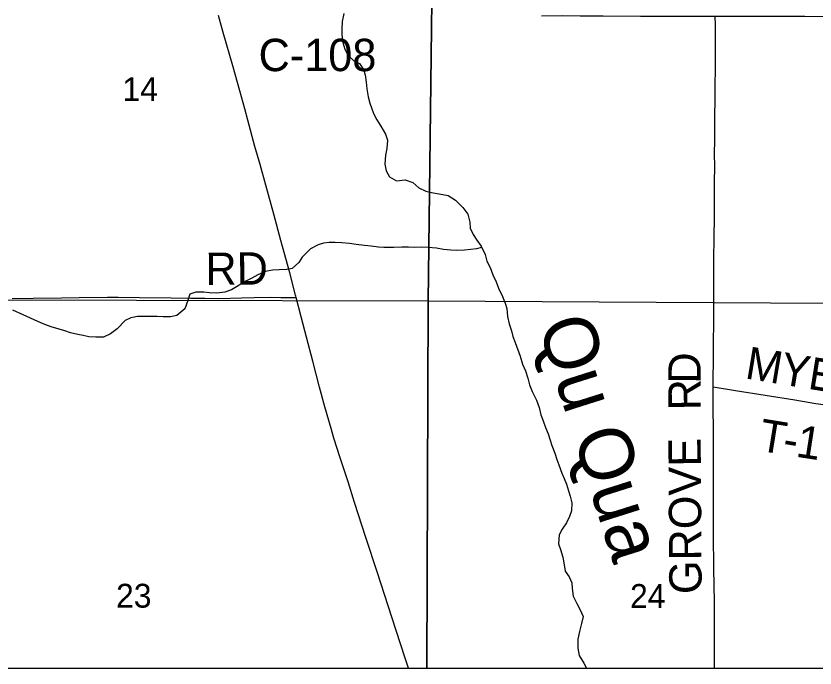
# Model space of a CAD drawing. Extents: x -9.1 to 34, y -3.1 to 22.
# Drawn here: x 6.461 to 7.865, y 14.1 to 15.245 of the extents above; entities that cross this region are included whole.
import ezdxf

# ---------------------------------------------------------------- set-up
doc = ezdxf.new("R2010")
doc.units = 0
for name, color, linetype in [('GM_X_County_Road', 7, 'Continuous'), ('GM_X_County_Road_Text', 7, 'Continuous'), ('GM_X_Minor_River', 7, 'Continuous'), ('GM_X_Minor_River_Text', 7, 'Continuous'), ('GM_X_Section', 7, 'Continuous'), ('GM_X_Section_Text', 7, 'Continuous'), ('GM_X_State_Route', 7, 'Continuous'), ('GM_X_Township', 7, 'Continuous'), ('GM_X_Township_Road', 7, 'Continuous'), ('GM_X_Township_Road_Text', 7, 'Continuous'), ('SH_Data', 7, 'Continuous')]:
    doc.layers.add(name, color=color, linetype=linetype)

msp = doc.modelspace()

# ---------------------------------------------------------------- linework, layer by layer
at = {"layer": 'GM_X_County_Road'}
for points in [[(7.3847, 15.2454), (7.4215, 15.2455), (7.4526, 15.2453), (7.4929, 15.2451), (7.5582, 15.2447), (7.6203, 15.2445), (7.6576, 15.2445), (7.6897, 15.2447)], [(7.6897, 15.2447), (7.6948, 15.2447), (7.757, 15.2443), (7.8098, 15.2443), (7.847, 15.2444), (7.8905, 15.244), (7.9185, 15.244), (7.9624, 15.2443)]]:
    msp.add_lwpolyline(points, dxfattribs=at)
at = {"layer": 'GM_X_Minor_River'}
for points in [[(7.0374, 15.2492), (7.0346, 15.2352), (7.0336, 15.2219), (7.0335, 15.2117), (7.0352, 15.1984), (7.0388, 15.1866), (7.0447, 15.1756), (7.0544, 15.1667), (7.065, 15.1616), (7.072, 15.1509), (7.0749, 15.1414), (7.0766, 15.1289), (7.0776, 15.1167), (7.0801, 15.1027), (7.0829, 15.092), (7.0862, 15.0821), (7.0902, 15.0722), (7.095, 15.0627), (7.1021, 15.0516), (7.1102, 15.0371), (7.1139, 15.0268), (7.1125, 15.012), (7.1105, 15.0003), (7.1091, 14.9848), (7.1116, 14.973), (7.1175, 14.9627), (7.1299, 14.9553), (7.1447, 14.957), (7.1586, 14.9527), (7.1691, 14.9434), (7.1812, 14.9372), (7.1914, 14.9348), (7.2046, 14.9327), (7.2205, 14.9298), (7.2336, 14.9217), (7.2463, 14.9083), (7.2548, 14.8968), (7.2584, 14.8827), (7.2594, 14.8721), (7.2646, 14.861), (7.2709, 14.8515), (7.2783, 14.8407), (7.2853, 14.8262), (7.2885, 14.8141), (7.2944, 14.803), (7.2992, 14.7901), (7.3051, 14.7782), (7.3087, 14.7672), (7.3157, 14.7523), (7.3205, 14.7409), (7.3234, 14.7314), (7.3247, 14.7173), (7.3279, 14.7044), (7.3319, 14.6918), (7.334, 14.6823), (7.338, 14.6717), (7.3468, 14.6473), (7.3512, 14.6336), (7.3563, 14.6218), (7.3607, 14.6088), (7.3635, 14.5974), (7.3683, 14.5856), (7.3756, 14.5703), (7.3804, 14.5574), (7.3836, 14.5448), (7.3876, 14.5338), (7.3916, 14.5224), (7.396, 14.5113), (7.4, 14.5003), (7.4029, 14.4908), (7.4077, 14.477), (7.4113, 14.4664)], [(7.2793, 14.8386), (7.2703, 14.8359), (7.2604, 14.8349), (7.249, 14.8339), (7.2358, 14.833), (7.2252, 14.8335), (7.2123, 14.8348), (7.1998, 14.8369), (7.1855, 14.8382), (7.1745, 14.8388), (7.1616, 14.8386), (7.151, 14.8387), (7.1393, 14.8392), (7.1248, 14.8383), (7.1078, 14.8382), (7.098, 14.8391), (7.0855, 14.8407), (7.0734, 14.842), (7.059, 14.8438), (7.0473, 14.8451), (7.0337, 14.8464), (7.0223, 14.8469), (7.0117, 14.8471), (7.0015, 14.8457), (6.992, 14.8432), (6.9786, 14.8358), (6.964, 14.8216), (6.9582, 14.8118), (6.9467, 14.8013), (6.9372, 14.8), (6.9239, 14.7994), (6.9122, 14.7988), (6.8996, 14.7963), (6.8863, 14.7904), (6.8756, 14.7845), (6.8649, 14.779), (6.8401, 14.7642), (6.8283, 14.7602), (6.8143, 14.7581), (6.801, 14.7586), (6.7912, 14.7599), (6.7772, 14.7601), (6.7669, 14.7564), (6.7633, 14.7451), (6.7582, 14.7304), (6.744, 14.7192), (6.733, 14.7167), (6.7201, 14.7165), (6.7091, 14.7171), (6.6868, 14.7174), (6.6747, 14.7172), (6.6633, 14.7151), (6.6534, 14.7103), (6.6388, 14.6957), (6.6276, 14.6867), (6.6151, 14.6809), (6.6018, 14.6807), (6.5893, 14.6816), (6.5795, 14.6836), (6.5697, 14.6856), (6.5572, 14.6888), (6.547, 14.692), (6.5372, 14.6948), (6.5233, 14.6992), (6.512, 14.7031), (6.4995, 14.7082), (6.4871, 14.7141), (6.474, 14.7203), (6.4559, 14.7281)], [(7.4113, 14.4664), (7.415, 14.4565), (7.4201, 14.4424), (7.4245, 14.4328), (7.4285, 14.4226), (7.4321, 14.4111), (7.435, 14.4016), (7.4379, 14.3898), (7.4369, 14.3762), (7.4334, 14.366), (7.4283, 14.3547), (7.421, 14.3438), (7.4155, 14.3337), (7.4142, 14.3178), (7.4178, 14.3083), (7.4218, 14.2946), (7.4242, 14.2813), (7.426, 14.2702), (7.433, 14.2599), (7.4378, 14.2496), (7.4384, 14.2398), (7.4401, 14.2261), (7.4468, 14.2135), (7.4519, 14.2036), (7.4574, 14.1902), (7.455, 14.1781), (7.4514, 14.1642), (7.4486, 14.1509), (7.4483, 14.1346), (7.4508, 14.1221), (7.459, 14.1087), (7.4633, 14.1)]]:
    msp.add_lwpolyline(points, dxfattribs=at)
at = {"layer": 'GM_X_Section'}
for p, q in [((6.1534, 14.1), (7.1831, 14.1)), ((7.1831, 14.1), (8.1826, 14.1))]:
    msp.add_line(p, q, dxfattribs=at)
for points in [[(6.1904, 15.7491), (7.1977, 15.7504), (7.1851, 14.7442), (6.1603, 14.7464)], [(7.1977, 15.7504), (7.6939, 15.7344), (8.1957, 15.7506), (8.1958, 15.7211), (8.1871, 14.738), (7.1851, 14.7442)]]:
    msp.add_lwpolyline(points, close=True, dxfattribs=at)
for points in [[(7.1831, 14.1), (7.1851, 14.7442), (6.1603, 14.7464), (6.1534, 14.1)], [(8.1826, 14.1), (8.1865, 14.7111), (8.1871, 14.738), (7.1851, 14.7442), (7.1831, 14.1)]]:
    msp.add_lwpolyline(points, dxfattribs=at)
at = {"layer": 'GM_X_State_Route'}
for points in [[(6.9268, 14.8504), (6.9143, 14.8969), (6.9003, 14.9479), (6.8903, 14.9838), (6.881, 15.0158), (6.8687, 15.0617), (6.8631, 15.0821), (6.8543, 15.1135), (6.842, 15.1574), (6.8254, 15.2156), (6.817, 15.246)], [(6.9526, 14.7547), (6.9421, 14.7936), (6.9296, 14.8399), (6.9268, 14.8504)], [(7.1507, 14.1), (7.1444, 14.1193), (7.1221, 14.1875), (7.1086, 14.2289), (7.0962, 14.2673), (7.0761, 14.3294), (7.0562, 14.3908), (7.0446, 14.4267), (7.0309, 14.4692), (7.0198, 14.5033), (7.0147, 14.5207), (7.004, 14.5583), (6.9947, 14.5931), (6.9829, 14.6387), (6.9716, 14.6808), (6.9625, 14.7169), (6.9536, 14.7508), (6.953, 14.7529), (6.9526, 14.7547)]]:
    msp.add_lwpolyline(points, dxfattribs=at)
at = {"layer": 'GM_X_Township'}
msp.add_lwpolyline([(2.6, 15.2819), (2.6, 14.1), (8.1877, 14.1)], dxfattribs=at)
at = {"layer": 'GM_X_Township_Road'}
for points in [[(7.6862, 14.5937), (7.6865, 14.6539), (7.6866, 14.6705), (7.6868, 14.6798), (7.687, 14.6983), (7.6872, 14.7262), (7.6873, 14.7666), (7.6874, 14.81), (7.6877, 14.8628), (7.6882, 14.8845), (7.6882, 14.9133), (7.6884, 14.9466), (7.6887, 14.9869), (7.6885, 14.9962), (7.6889, 15.0334), (7.689, 15.0521), (7.6892, 15.0707), (7.6893, 15.0956), (7.6893, 15.1234), (7.6899, 15.1513), (7.69, 15.1669), (7.6901, 15.1824), (7.6899, 15.2059), (7.6899, 15.2212), (7.69, 15.2319), (7.6898, 15.2418), (7.6897, 15.2447)], [(6.4545, 14.7488), (6.4917, 14.7493), (6.5414, 14.7502), (6.5725, 14.7504), (6.6222, 14.7509), (6.6408, 14.7509), (6.6781, 14.7506), (6.734, 14.75), (6.7682, 14.7494), (6.793, 14.7492), (6.8178, 14.749), (6.8582, 14.7497), (6.8799, 14.7503), (6.9079, 14.7509), (6.9264, 14.7508), (6.9495, 14.7508), (6.9536, 14.7508)], [(7.6862, 14.5937), (7.7252, 14.5875), (7.7774, 14.579), (7.8295, 14.5706), (7.8664, 14.5647), (7.8972, 14.5603), (7.9497, 14.554), (7.9775, 14.5509), (8.0115, 14.5478), (8.0394, 14.5454), (8.0735, 14.5423), (8.1138, 14.539), (8.1323, 14.5373)], [(7.6884, 14.1), (7.6884, 14.1107), (7.6883, 14.1573), (7.6882, 14.2164), (7.6871, 14.2743), (7.6869, 14.3348), (7.6867, 14.425), (7.6864, 14.5016), (7.6862, 14.5727), (7.6862, 14.5937)]]:
    msp.add_lwpolyline(points, dxfattribs=at)
at = {"layer": 'SH_Data'}
msp.add_line((2.6, 14.1), (9.4, 14.1), dxfattribs=at)

# ---------------------------------------------------------------- texts
at = {"layer": 'GM_X_County_Road_Text'}
msp.add_text('C-108', height=0.05682, rotation=0, dxfattribs=at).set_placement((6.8875, 15.148))
at = {"layer": 'GM_X_Minor_River_Text'}
msp.add_text('Qu Qua', height=0.09471, rotation=287.5789, dxfattribs=at).set_placement((7.3775, 14.703))
at = {"layer": 'GM_X_Section_Text'}
for s, p in [('14', (6.6483, 15.0955)), ('23', (6.6371, 14.206)), ('24', (7.54, 14.2055))]:
    msp.add_text(s, height=0.04186, rotation=0, dxfattribs=at).set_placement(p)
at = {"layer": 'GM_X_Township_Road_Text'}
for s, height, rotation, p in [('RD', 0.05682, 0.4759, (6.7943, 14.7725)), ('M', 0.0568, 350.5828, (7.7404, 14.6088)), ('Y', 0.0568, 350.59, (7.8012, 14.5987)), ('D', 0.0568, 89.4354, (7.6638, 14.5991)), ('E', 0.0568, 350.9822, (7.8509, 14.5905)), ('R', 0.0568, 90.6791, (7.6644, 14.5527)), ('T', 0.0568, 350.7498, (7.7641, 14.4819)), ('1', 0.0568, 351.1614, (7.8296, 14.4713)), ('GROVE', 0.05682, 90.3851, (7.666, 14.2299)), ('-', 0.0568, 350.8277, (7.8062, 14.4751))]:
    msp.add_text(s, height=height, rotation=rotation, dxfattribs=at).set_placement(p)

doc.saveas('drawing.dxf')
